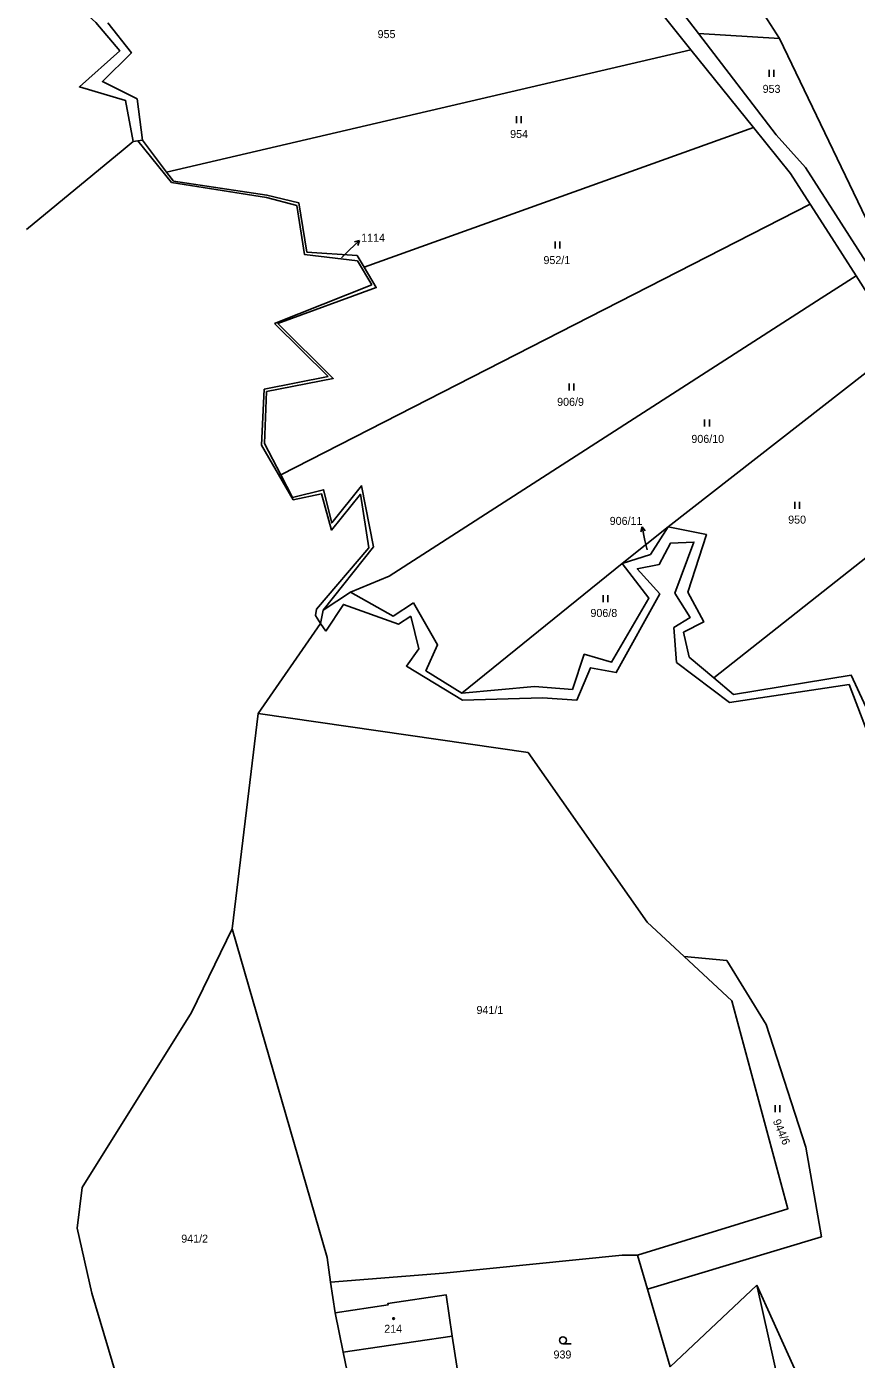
# Model space of a CAD drawing. Extents: x -680203 to -673936, y -1102717 to -1093650.
# Drawn here: x -679937.5 to -679761.2, y -1097519.2 to -1097236 of the extents above; entities that cross this region are included whole.
import ezdxf

# ---------------------------------------------------------------- set-up
doc = ezdxf.new("R2010")
doc.units = 0
for name, color, linetype in [('SOxx02xx_Staničení_Popis10', 7, 'Continuous'), ('SOxxxxxx_Koleje_hlavní_body_Popis10', 7, 'Continuous'), ('SOxxxxxx_Koleje_param další_Popis10', 7, 'Continuous'), ('SOxxxxxx_Osa_bod_P', 7, 'Continuous'), ('SOxxxxxx_Staničení_Popis10', 7, 'Continuous'), ('x_prac', 7, 'Continuous')]:
    doc.layers.add(name, color=color, linetype=linetype)

msp = doc.modelspace()

# ---------------------------------------------------------------- linework, layer by layer
at = {"layer": 'SOxx02xx_Staničení_Popis10'}
for p, q in [((-679868.94, -1097283.48), (-679866.78, -1097281.4)), ((-679866.78, -1097281.4), (-679867.85, -1097281.73)), ((-679866.78, -1097281.4), (-679867.15, -1097282.45)), ((-679870.61, -1097285.11), (-679868.94, -1097283.48)), ((-679806.72, -1097342.26), (-679807.01, -1097343.34)), ((-679806.1, -1097345.19), (-679806.72, -1097342.26)), ((-679806.72, -1097342.26), (-679806.03, -1097343.13)), ((-679805.67, -1097347.16), (-679806.1, -1097345.19))]:
    msp.add_line(p, q, dxfattribs=at)
at = {"layer": 'SOxxxxxx_Koleje_hlavní_body_Popis10'}
for p, q in [((-679779.72, -1097246.63), (-679779.72, -1097245.13)), ((-679778.72, -1097246.63), (-679778.72, -1097245.13)), ((-679833.41, -1097256.51), (-679833.41, -1097255.01)), ((-679832.41, -1097256.51), (-679832.41, -1097255.01)), ((-679825.22, -1097283.13), (-679825.22, -1097281.63)), ((-679824.22, -1097283.13), (-679824.22, -1097281.63)), ((-679822.19, -1097313.27), (-679822.19, -1097311.77)), ((-679821.19, -1097313.27), (-679821.19, -1097311.77)), ((-679793.42, -1097320.92), (-679793.42, -1097319.42)), ((-679792.42, -1097320.92), (-679792.42, -1097319.42)), ((-679774.29, -1097338.46), (-679774.29, -1097336.96)), ((-679773.29, -1097338.46), (-679773.29, -1097336.96)), ((-679815.02, -1097358.28), (-679815.02, -1097356.78)), ((-679814.02, -1097358.28), (-679814.02, -1097356.78)), ((-679778.44, -1097466.63), (-679778.44, -1097465.13)), ((-679777.44, -1097466.63), (-679777.44, -1097465.13)), ((-679823.54, -1097515.85), (-679821.79, -1097515.85))]:
    msp.add_line(p, q, dxfattribs=at)
msp.add_circle((-679823.54, -1097515.1), 0.75, dxfattribs=at)
at = {"layer": 'SOxxxxxx_Koleje_param další_Popis10'}
msp.add_circle((-679859.54, -1097510.48), 0.175, dxfattribs=at)
at = {"layer": 'SOxxxxxx_Staničení_Popis10'}
msp.add_line((-679847.05, -1097514.2), (-679870.24, -1097517.66), dxfattribs=at)
at = {"layer": 'x_prac'}
for p, q in [((-679794.73, -1097237.43), (-679777.52, -1097238.49)), ((-679751.35, -1097293.04), (-679777.52, -1097238.49)), ((-679796.34, -1097240.87), (-679907.77, -1097266.88)), ((-679796.34, -1097240.87), (-679783.07, -1097257.42)), ((-679783.07, -1097257.42), (-679865.81, -1097287.11)), ((-679914.86, -1097260.39), (-679916.99, -1097262.14)), ((-679914.86, -1097260.39), (-679913.87, -1097260.26)), ((-679913.87, -1097260.26), (-679912.88, -1097260.13)), ((-679913.87, -1097260.26), (-679906.7, -1097269.12)), ((-679907.77, -1097266.88), (-679912.88, -1097260.13)), ((-679916.99, -1097262.14), (-679937.56, -1097279.09)), ((-679906.7, -1097269.12), (-679886.55, -1097272.25)), ((-679886.55, -1097272.25), (-679880.08, -1097273.99)), ((-679771.03, -1097273.72), (-679883.52, -1097331.23)), ((-679867.22, -1097285.76), (-679864.17, -1097290.81)), ((-679864.17, -1097290.81), (-679884.83, -1097299.08)), ((-679884.83, -1097299.08), (-679873.41, -1097310.35)), ((-679873.41, -1097310.35), (-679887.01, -1097312.99)), ((-679887.01, -1097312.99), (-679887.64, -1097324.93)), ((-679887.64, -1097324.93), (-679880.88, -1097336.55)), ((-679883.52, -1097331.23), (-679886.97, -1097324.58)), ((-679881, -1097336.06), (-679883.52, -1097331.23)), ((-679736.92, -1097331.22), (-679791.48, -1097374.33)), ((-679801.17, -1097342.28), (-679810.93, -1097350.03)), ((-679864.77, -1097346.72), (-679875.89, -1097359.73)), ((-679810.93, -1097350.03), (-679845.03, -1097377.58)), ((-679868.7, -1097356.11), (-679874.5, -1097360)), ((-679875.89, -1097359.73), (-679876.16, -1097361.11)), ((-679876.16, -1097361.11), (-679875.04, -1097362.78)), ((-679875.04, -1097362.78), (-679874.5, -1097360)), ((-679875.04, -1097362.78), (-679888.28, -1097381.91)), ((-679873.94, -1097364.43), (-679875.04, -1097362.78)), ((-679888.28, -1097381.91), (-679893.84, -1097427.69)), ((-679893.84, -1097427.69), (-679902.47, -1097445.45)), ((-679902.47, -1097445.45), (-679925.7, -1097482.65)), ((-679925.7, -1097482.65), (-679926.79, -1097491.31)), ((-679926.79, -1097491.31), (-679923.68, -1097505.11)), ((-679805.59, -1097504.27), (-679807.71, -1097497.02)), ((-679848.9, -1097500.88), (-679872.94, -1097502.75)), ((-679872.94, -1097502.75), (-679871.96, -1097509.27)), ((-679782.31, -1097503.4), (-679800.78, -1097520.73)), ((-679774.17, -1097540.07), (-679782.31, -1097503.4)), ((-679923.68, -1097505.11), (-679916.8, -1097528.04)), ((-679800.78, -1097520.73), (-679805.59, -1097504.27))]:
    msp.add_line(p, q, dxfattribs=at)
for points in [[(-679777.52, -1097238.49), (-679811.29, -1097185.84), (-679838.11, -1097140.79)], [(-679870.58, -1097153.87), (-679857.76, -1097170.29), (-679848.4, -1097180.66), (-679825.31, -1097204.05), (-679807.65, -1097222.26), (-679803.36, -1097226.17), (-679794.73, -1097237.43)], [(-679914.86, -1097260.39), (-679916.5, -1097251.67), (-679926.3, -1097248.8), (-679917.75, -1097241.1), (-679922.83, -1097235.07), (-679933.55, -1097225.31), (-679930.1, -1097207.25), (-679930.28, -1097193.67)], [(-679825.5, -1097211.31), (-679808.79, -1097225.33), (-679796.34, -1097240.87)], [(-679912.88, -1097260.13), (-679914.02, -1097251.34), (-679921.42, -1097247.64), (-679915.25, -1097241.56), (-679920.25, -1097235.14)], [(-679794.73, -1097237.43), (-679778.21, -1097258.98), (-679772.01, -1097265.92), (-679753.31, -1097295.07), (-679742.63, -1097308.05)], [(-679783.07, -1097257.42), (-679775.2, -1097267.21), (-679771.03, -1097273.72)], [(-679865.81, -1097287.11), (-679867.3, -1097284.64), (-679877.97, -1097283.89), (-679879.66, -1097273.42), (-679886.45, -1097271.76), (-679906.3, -1097268.82), (-679907.77, -1097266.88)], [(-679880.08, -1097273.99), (-679878.5, -1097284.36), (-679867.22, -1097285.76)], [(-679761.22, -1097288.91), (-679767.06, -1097279.89), (-679771.03, -1097273.72)], [(-679886.97, -1097324.58), (-679886.51, -1097313.51), (-679872.35, -1097310.72), (-679884.12, -1097299.07), (-679863.22, -1097291.41), (-679865.81, -1097287.11)], [(-679868.7, -1097356.11), (-679860.44, -1097352.75), (-679768.63, -1097293.66), (-679761.22, -1097288.91)], [(-679721.02, -1097339.35), (-679756.04, -1097297.04), (-679761.22, -1097288.91)], [(-679801.17, -1097342.28), (-679759.07, -1097309.45), (-679752.1, -1097319.77), (-679740.21, -1097327.05), (-679736.92, -1097331.22)], [(-679874.5, -1097360), (-679863.79, -1097346.52), (-679866.34, -1097333.54), (-679872.69, -1097341.42), (-679874.41, -1097334.38), (-679881, -1097336.06)], [(-679880.88, -1097336.55), (-679874.83, -1097335.27), (-679872.7, -1097342.94), (-679866.57, -1097335.32), (-679864.77, -1097346.72)], [(-679810.93, -1097350.03), (-679804.94, -1097348.15), (-679801.17, -1097342.28)], [(-679791.48, -1097374.33), (-679796.71, -1097369.93), (-679797.91, -1097364.66), (-679793.61, -1097362.48), (-679796.97, -1097356.17), (-679793.05, -1097343.92), (-679801.17, -1097342.28)], [(-679753.82, -1097402.13), (-679755.13, -1097395.59), (-679762.71, -1097375.78), (-679788.12, -1097379.62), (-679799.41, -1097371.07), (-679799.98, -1097363.68), (-679796.48, -1097361.5), (-679799.77, -1097356.37), (-679795.71, -1097345.5), (-679800.67, -1097345.73), (-679803.06, -1097350.26), (-679807.75, -1097351.16), (-679802.97, -1097356.52), (-679812.21, -1097373.24), (-679817.66, -1097372.2), (-679820.57, -1097379.08), (-679827.91, -1097378.61), (-679844.9, -1097379.07), (-679856.82, -1097371.84), (-679854.14, -1097368.15), (-679855.87, -1097361.21)], [(-679845.03, -1097377.58), (-679829.57, -1097376.16), (-679821.51, -1097376.79), (-679819.01, -1097369.34), (-679813.25, -1097371.04), (-679805.25, -1097357.39), (-679810.93, -1097350.03)], [(-679855.28, -1097358.44), (-679859.6, -1097361.24), (-679868.7, -1097356.11)], [(-679855.87, -1097361.21), (-679858.52, -1097362.92), (-679870.18, -1097358.73), (-679873.94, -1097364.43)], [(-679845.03, -1097377.58), (-679852.65, -1097372.85), (-679850.2, -1097367.34), (-679855.28, -1097358.44)], [(-679791.48, -1097374.33), (-679787.3, -1097377.89), (-679762.26, -1097373.81), (-679752.36, -1097395.18), (-679752.12, -1097404.6)], [(-679797.75, -1097433.57), (-679805.65, -1097426.23), (-679830.94, -1097390.23), (-679888.28, -1097381.91)], [(-679893.84, -1097427.69), (-679873.67, -1097497.55), (-679872.94, -1097502.75)], [(-679807.71, -1097497.02), (-679775.74, -1097487.15), (-679787.63, -1097442.98), (-679797.75, -1097433.57)], [(-679797.75, -1097433.57), (-679788.73, -1097434.42), (-679780.36, -1097448.01), (-679771.89, -1097474.05), (-679768.6, -1097493.09), (-679805.59, -1097504.27)], [(-679807.71, -1097497.02), (-679810.94, -1097497.01), (-679848.9, -1097500.88)], [(-679782.31, -1097503.4), (-679772.33, -1097525.51), (-679774.17, -1097540.07)], [(-679862.66, -1097537.85), (-679851.56, -1097534.94), (-679853.1, -1097529.07), (-679845.12, -1097526.98), (-679847.05, -1097514.2), (-679848.37, -1097505.43), (-679860.75, -1097507.29), (-679860.69, -1097507.58), (-679871.96, -1097509.27)], [(-679871.96, -1097509.27), (-679870.24, -1097517.66), (-679868.21, -1097527.54), (-679909.52, -1097545.58)]]:
    msp.add_lwpolyline(points, dxfattribs=at)

# ---------------------------------------------------------------- texts
at = {"layer": 'SOxxxxxx_Osa_bod_P'}
for s, p in [('955', (-679862.93, -1097238.41)), ('953', (-679781.1, -1097250.05)), ('954', (-679834.76, -1097259.64)), ('1114', (-679866.42, -1097281.68)), ('952/1', (-679827.68, -1097286.43)), ('906/9', (-679824.77, -1097316.55)), ('906/10', (-679796.24, -1097324.42)), ('906/11', (-679813.6, -1097341.85)), ('950', (-679775.67, -1097341.58)), ('906/8', (-679817.69, -1097361.41)), ('941/1', (-679841.91, -1097445.78)), ('941/2', (-679904.66, -1097494.36)), ('214', (-679861.52, -1097513.51)), ('939', (-679825.54, -1097518.98))]:
    msp.add_text(s, height=1.7, dxfattribs=at).set_placement(p)
msp.add_text('944/6', height=1.7, rotation=293, dxfattribs=at).set_placement((-679778.96, -1097468.54))

doc.saveas('drawing.dxf')
